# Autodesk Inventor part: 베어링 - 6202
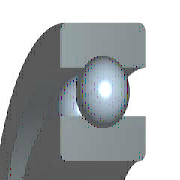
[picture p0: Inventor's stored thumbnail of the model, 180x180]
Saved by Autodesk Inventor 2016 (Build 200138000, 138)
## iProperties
IsCustomPart: 1
Created: 2015-09
Part Number: 베어링 - 6202
Material: 강, 연강
Description: 깊은 그루브 볼 베어링
Document SubType Name: Modeling
Standard: KS B 2023
Designer: mduedu
Standards Organization: KS
Language: ko-KR
Size Designation: 6202 - 15 x 35 x 11
Categories: <MemberInstance><Categories><Category DisplayName="샤프트 부품" InternalName="7f7aeb1f-a693-4053-b835-cee3144e0d98" Mnemonic="SHFT"><Category DisplayName="베어링" Inter
Density: 7.86 g/cm^3
Mass: 45.8725 g
Surface Area: 51.5584 cm^2
Volume: 5.83619 cm^3
Appearance: 크롬 - 광택
Author: mduedu
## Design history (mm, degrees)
sketch "스케치" dims "d0" = 5.2 (= -0.26 x WD + 0.26 x BD)
  geometry: L1 (2.9, 12.5)-(8.1, 12.5); L2 (5.5, 12.5)-(5.5, 9.9); L3 (5.5, 12.5)-(5.5, 15.1); L4 (3.568, 10.76)-(0, 10.76); L5 (0, 7.5)-(11, 7.5); L6 (3.568, 14.24)-(0, 14.24); L7 (0, 17.5)-(11, 17.5); L8 (11, 7.5)-(11, 10.76); L9 (7.432, 10.76)-(11, 10.76); L10 (7.432, 14.24)-(11, 14.24); L11 (11, 17.5)-(11, 14.24); L12 (-1.4, 0)-(8.4, 0) reference; L13 (0, -0.3)-(0, 5.3) reference
  constraints: 22 end point, 4 point on line, 2 collinear, 2 perpendicular, 2 symmetric about line, 1 midpoint, 1 parallel, 14 other
  dimensions: "d9" = 15 diameter of L5 L12 (= WD); "d11" = 35 diameter of L7 L12 (= BD); "d12" = 11 distance between parallel lines of L8 L13 (= KB); "d13" = 21.52 diameter of L9 L12 (= 0.326 x BD + 0.674 x WD)
revolve "본체" stored, may be unused: angle "d6" = 90 deg
revolve "볼" stored, may be unused: angle "d7" = 90 deg
pattern_circular "IDS_ARRAYBALL[SIMPL:T]" dims angle "d3" = 360 deg
body "Solid1"
fillet "모깎기1" dims "d1" = 0.6 (= KRS)
other parameters: "WD" = 15 [user parameter; used in 5 equation terms], "BD" = 35 [user parameter; used in 5 equation terms], "KB" = 11 [user parameter; used in 1 equation term], "KRS" = 0.6 [user parameter; used in 1 equation term], "d4" = 0, "d5" = 0, "d8" = 0, "d14" = 0, "d15" = 0, "BBA" = 0 [user parameter], "BC0" = 3750000 [user parameter], "BC" = 7800000 [user parameter], "BR" = 17.5 (= 0.5 x BD) [user parameter], "WR" = 7.5 (= 0.5 x WD) [user parameter]
